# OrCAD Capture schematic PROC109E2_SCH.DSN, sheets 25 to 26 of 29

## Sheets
25 25. SOC_ANALOG_POWER_DECAPs: size C; title: SoC Analog POWER & DECAPs
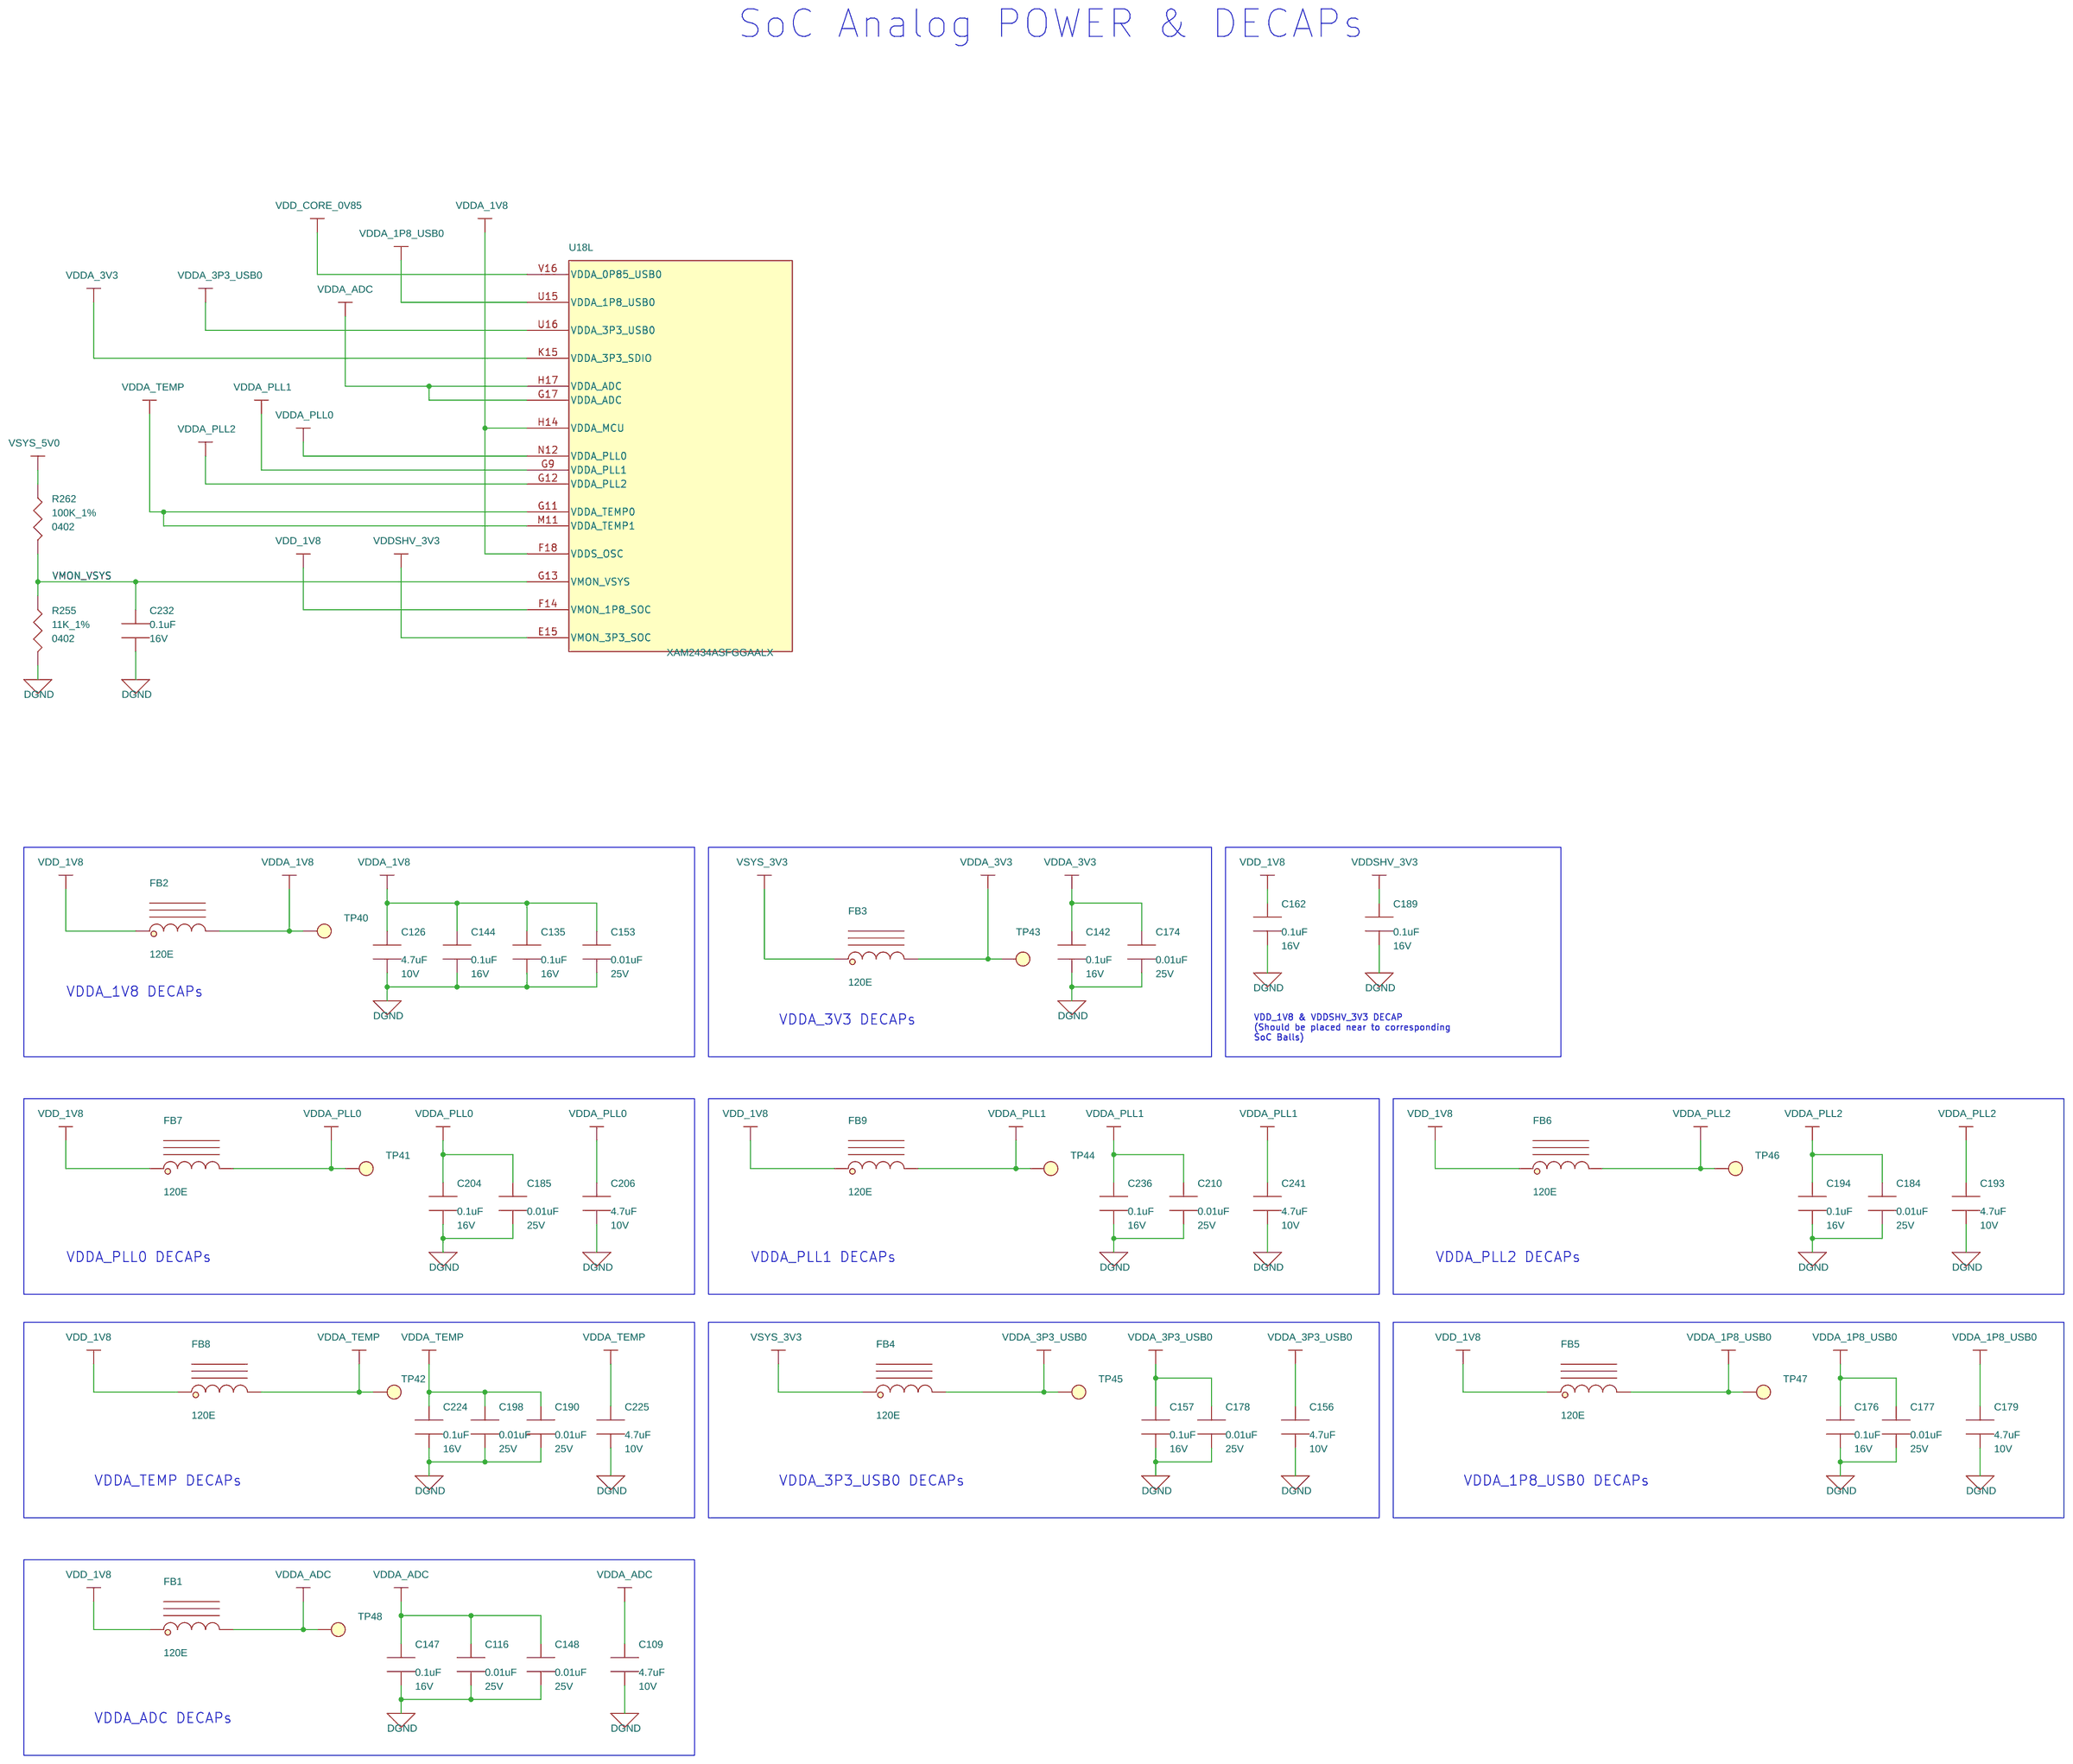
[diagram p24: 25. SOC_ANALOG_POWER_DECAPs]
26 26. BOARD_POWER_IN_TYPE_C: size C; title: BOARD POWER INPUT & USB2.0
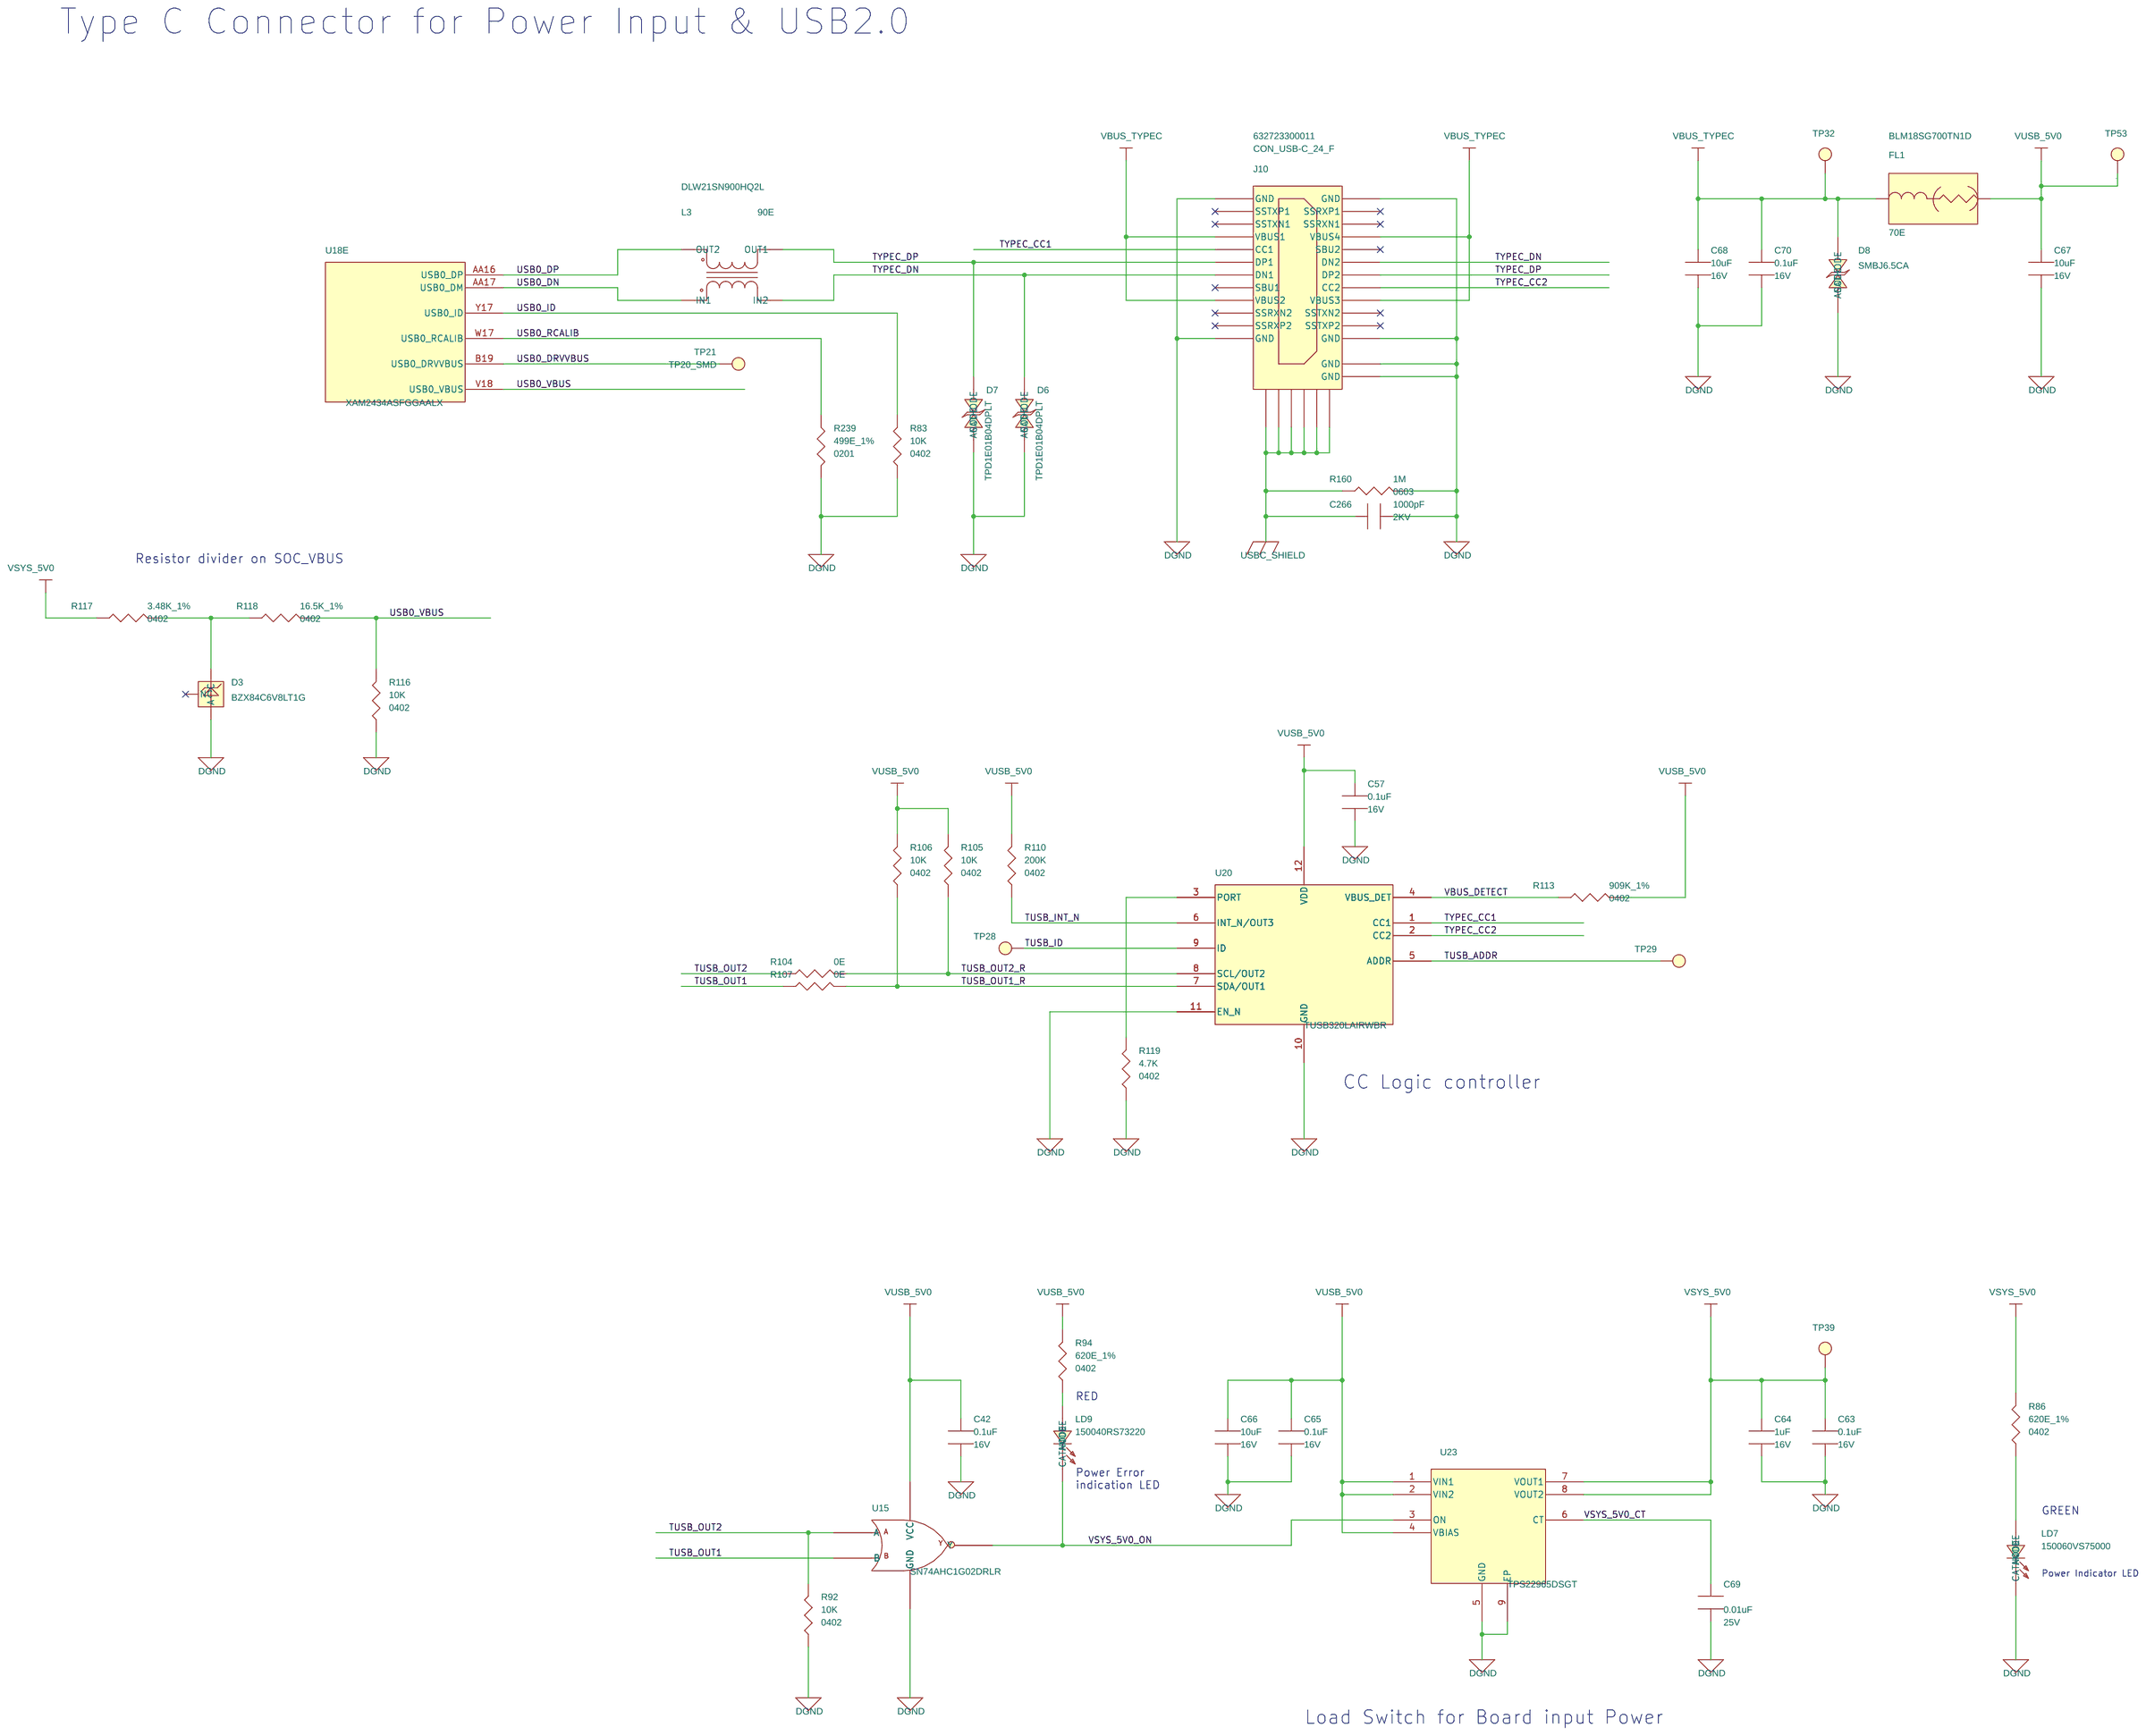
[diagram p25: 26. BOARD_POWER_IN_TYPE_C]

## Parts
sheet 15. SOC_QSPI_BOARD_ID_EEPROM
U18  XAM2434ASFGGAALX  [BGA293_19-68_440X440_1]  (sections A,B,C,D,E,F,G,H,I,J,K,L,M)
sheet 25. SOC_ANALOG_POWER_DECAPs
C109  4.7uF  [CAP0402_0-75]
C116  0.01uF  [CAP0201_0-5]
C126  4.7uF  [CAP0402_0-75]
C135  0.1uF  [CAP0201_0-5]
C142  0.1uF  [CAP0201_0-5]
C144  0.1uF  [CAP0201_0-5]
C147  0.1uF  [CAP0201_0-5]
C148  0.01uF  [CAP0201_0-5]
C153  0.01uF  [CAP0201_0-5]
C156  4.7uF  [CAP0402_0-75]
C157  0.1uF  [CAP0201_0-5]
C162  0.1uF  [CAP0201_0-5]
C174  0.01uF  [CAP0201_0-5]
C176  0.1uF  [CAP0201_0-5]
C177  0.01uF  [CAP0201_0-5]
C178  0.01uF  [CAP0201_0-5]
C179  4.7uF  [CAP0402_0-75]
C184  0.01uF  [CAP0201_0-5]
C185  0.01uF  [CAP0201_0-5]
C189  0.1uF  [CAP0201_0-5]
C190  0.01uF  [CAP0201_0-5]
C193  4.7uF  [CAP0402_0-75]
C194  0.1uF  [CAP0201_0-5]
C198  0.01uF  [CAP0201_0-5]
C204  0.1uF  [CAP0201_0-5]
C206  4.7uF  [CAP0402_0-75]
C210  0.01uF  [CAP0201_0-5]
C224  0.1uF  [CAP0201_0-5]
C225  4.7uF  [CAP0402_0-75]
C232  0.1uF  [CAP0201_0-5]
C236  0.1uF  [CAP0201_0-5]
C241  4.7uF  [CAP0402_0-75]
FB1  120E  [IND0603_1]
FB2  120E  [IND0603_1]
FB3  120E  [IND0603_1]
FB4  120E  [IND0603_1]
FB5  120E  [IND0603_1]
FB6  120E  [IND0603_1]
FB7  120E  [IND0603_1]
FB8  120E  [IND0603_1]
FB9  120E  [IND0603_1]
R255  11K_1%  [RES0402_0-5]
R262  100K_1%  [RES0402_0-5]
TP40  TP20_SMD  [TP20_SMD]
TP41  TP20_SMD  [TP20_SMD]
TP42  TP20_SMD  [TP20_SMD]
TP43  TP20_SMD  [TP20_SMD]
TP44  TP20_SMD  [TP20_SMD]
TP45  TP20_SMD  [TP20_SMD]
TP46  TP20_SMD  [TP20_SMD]
TP47  TP20_SMD  [TP20_SMD]
TP48  TP20_SMD  [TP20_SMD]
sheet 26. BOARD_POWER_IN_TYPE_C
C42  0.1uF  [CAP0201_0-5]
C57  0.1uF  [CAP0201_0-5]
C63  0.1uF  [CAP0201_0-5]
C64  1uF  [CAP0201_0-5]
C65  0.1uF  [CAP0201_0-5]
C66  10uF  [CAP0603_1]
C67  10uF  [CAP0603_1]
C68  10uF  [CAP0603_1]
C69  0.01uF  [CAP0201_0-5]
C70  0.1uF  [CAP0201_0-5]
C266  1000pF  [CAP1210_1-5]
D3  BZX84C6V8LT1G  [SOT23-123_1-2]
D6  TPD1E01B04DPLT  [DIO_DFN0201_0-4]
D7  TPD1E01B04DPLT  [DIO_DFN0201_0-4]
D8  SMBJ6.5CA  [DIO_SMB_2-7]
FL1  70E  [EMIFIL_BLM18B_0603_0-7]
J10  CON_USB-C_24_F  [CON_USBC24_6327233_S_R_S_3-1]
L3  90E  [IND4_DLW21H_90X60_SMD_1-4]
LD7  150060VS75000  [LED_150060SS75000_70X40_SMD_0-8]
LD9  150040RS73220  [LED_150040GS73220_40X20_SMD_0-4]
R83  10K  [RES0402_0-5]
R86  620E_1%  [RES0402_0-5]
R92  10K  [RES0402_0-5]
R94  620E_1%  [RES0402_0-5]
R104  0E  [RES0402_0-5]
R105  10K  [RES0402_0-5]
R106  10K  [RES0402_0-5]
R107  0E  [RES0402_0-5]
R110  200K  [RES0402_0-5]
R113  909K_1%  [RES0402_0-5]
R116  10K  [RES0402_0-5]
R117  3.48K_1%  [RES0402_0-5]
R118  16.5K_1%  [RES0402_0-5]
R119  4.7K  [RES0402_0-5]
R160  1M  [RES0603_0-75]
R239  499E_1%  [RES0201_0-5]
TP21  TP20_SMD  [TP20_SMD]
TP28  TP20_SMD  [TP20_SMD]
TP29  TP20_SMD  [TP20_SMD]
TP32  TP40_SMD  [TP40_SMD]
TP39  TP40_SMD  [TP40_SMD]
TP53  TP40_SMD  [TP40_SMD]
U15  SN74AHC1G02DRLR  [SOT553-5_0-6]
U20  TUSB320LAIRWBR  [X2QFN12_TUSB322I_60X60_0-4]
U23  TPS22965DSGT  [WSON8_19-68_80X80_0-8]

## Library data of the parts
U18 = AM243X_SOC_LP_EVM_BGA293: IC AM243x SoC_LP_EVM MICROPROCESSOR BGA293; Chkd/date: MANIRAJA/131120; Crtd /date: ALVY/121120; Custom_Duty: 15%; Customs_HS_Code: 85423100; Distributor_name: NA; Distributor_part_number: NA; Footprint Path: Y:\MIS_DATABASE\Library\ALTIUM_TOOL\PCB_FOOTPRINTS\Altium_Footprint_Lib.PcbLib; Height: 1.00MM; Library Path: Y:\MIS_DATABASE\Library\ALTIUM_TOOL\SCHEMATICS_PARTS\MS_MICROPROCESSOR_Library.schlib; Library Ref: AM243x SoC_LP_EVM_BGA293; Mfr_name: TEXAS INSTRUMENTS; Mistral Part No: 141220110003; Package: BGA293; Part_type: ICS\DIGITAL\MICROPROCESSOR; Project: TI_AM243x LP EVM; RoHS: NA; Temperature: NA; Tolerance: NA; Voltage: NA; Wattage: NA; Weight: NA; Datasheet: Y:\MIS_DATABASE\DATASHEETS\ICS\DIGITAL\MICROCONTROLLER\AM243x SoC-FP.PDF
C109 C126 C156 C179 C193 C206 C225 C241 = CAP: CAP CERAMIC 4.7uF 10V 20% X5R 0402; Chkd/date: MANIRAJA/110718; Crtd /date: ALVY/110718; Custom_Duty: 15%; Customs_HS_Code: 85322990; Distributor_name: DIGIKEY; Distributor_part_number: 490-14306-1-ND; Footprint Path: Y:\MIS_DATABASE\Library\ALTIUM_TOOL\PCB_FOOTPRINTS\Altium_Footprint_Lib.PcbLib; Height: 0.65MM; Library Path: Y:\MIS_DATABASE\Library\ALTIUM_TOOL\SCHEMATICS_PARTS\MS_DISCRETE_Library.schlib; Mfr_name: MURATA; Mfr_part_number: GRM155R61A475MEAAD; Mistral Part No: 120012060002-R; Package: 0402; Part_type: CAPACITORS\CERAMIC; Project: TI_J7SVB_PCIE_ADD-ON-CARD; RoHS: RoHS; Temperature: -55°C+85°C; Tolerance: 20%; Voltage: 10V; Wattage: NA; Weight: 14mg; Datasheet: Y:\MIS_DATABASE\DATASHEETS\CAPACITORS\GRM155R61A475MEAAD.PDF
C69 C116 C148 C153 C174 C177 C178 C184 C185 C190 C198 C210 = CAP: CAP CERAMIC 0.01uF 25V 10% X7R 0201; Chkd/date: MANIRAJA/080519; Crtd /date: ALVY/080519; Custom_Duty: 15%; Customs_HS_Code: 85322990; Distributor_name: DIGIKEY; Distributor_part_number: 490-14454-1-ND; Footprint Path: Y:\MIS_DATABASE\Library\ALTIUM_TOOL\PCB_FOOTPRINTS\Altium_Footprint_Lib.PcbLib; Height: 0.33MM; Library Path: Y:\MIS_DATABASE\Library\ALTIUM_TOOL\SCHEMATICS_PARTS\MS_DISCRETE_Library.schlib; Mfr_name: MURATA; Mfr_part_number: GRM033R71E103KE14D; Mistral Part No: 120019050002-R; Package: 0201; Part_type: CAPACITORS\CERAMIC; Project: BRUKER_SD820_COMMONDO; RoHS: RoHS; Temperature: -55°C+125°C; Tolerance: 10%; Voltage: 25V; Wattage: NA; Weight: 0.33mg; Datasheet: Y:\MIS_DATABASE\DATASHEETS\CAPACITORS\GRM033R71E103KE14.PDF
C42 C57 C63 C65 C70 C135 C142 C144 C147 C157 C162 C176 C189 C194 C204 C224 C232 C236 = CAP: CAP CERAMIC 0.1uF 16V 10% X5R 0201; Chkd/date: MANIRAJA/230118; Crtd /date: MANIRAJA/230118; Custom_Duty: 15%; Customs_HS_Code: 85322990; Distributor_name: DIGIKEY; Distributor_part_number: 490-14305-1-ND; Footprint Path: Y:\MIS_DATABASE\Library\ALTIUM_TOOL\PCB_FOOTPRINTS\Altium_Footprint_Lib.PcbLib; Height: 0.33MM; Library Path: Y:\MIS_DATABASE\Library\ALTIUM_TOOL\SCHEMATICS_PARTS\MS_DISCRETE_Library.schlib; Mfr_name: MURATA; Mfr_part_number: GRM033R61C104KE14D; Mistral Part No: 120009030072-R; Package: 0201; Part_type: CAPACITORS\CERAMIC; Project: TI_MAXIE_CPB; RoHS: RoHS; Temperature: -55°C+85°C; Tolerance: 10%; Voltage: 16V; Wattage: NA; Weight: 0.33mg; Datasheet: Y:\MIS_DATABASE\DATASHEETS\CAPACITORS\GRM033R61C104KE14.PDF
FB1-FB9 = INDUCTOR_FERRITE: IND FERRITE BEAD CHIP 120E 2A 0603; Chkd/date: MANIRAJA/180820; Crtd /date: ALVY/180820; Custom_Duty: 24%; Customs_HS_Code: 85437099; Distributor_name: DIGIKEY; Distributor_part_number: 732-782631141CT-ND; Footprint Path: Y:\MIS_DATABASE\Library\ALTIUM_TOOL\PCB_FOOTPRINTS\Altium_Footprint_Lib.PcbLib; Height: 1.00MM; Library Path: Y:\MIS_DATABASE\Library\ALTIUM_TOOL\SCHEMATICS_PARTS\MS_FILTER_Library.schlib; Mfr_name: WURTH ELECTRONICS; Mfr_part_number: 782631141; Mistral Part No: 130020080015-R; Package: 0603; Part_type: INDUCTOR; Project: AM64x_EVM_BRD; RoHS: RoHS; Temperature: -55°C+125°C; Tolerance: 25%; Voltage: NA; Wattage: NA; Weight: NA; Datasheet: Y:\MIS_DATABASE\DATASHEETS\DISCRETES\INDUCTORS\782631141.PDF
R255 = RESISTOR: RES 11K 1/16W 1% 0402; Chkd/date: VASANTHA/251115; Crtd /date: VASANTHA/251115; Custom_Duty: 15%; Customs_HS_Code: 85332119; Distributor_name: DIGIKEY; Distributor_part_number: 311-11.0KLRCT-ND; Footprint Path: Y:\MIS_DATABASE\Library\ALTIUM_TOOL\PCB_FOOTPRINTS\Altium_Footprint_Lib.PcbLib; Height: 0.40MM; Library Path: Y:\MIS_DATABASE\Library\ALTIUM_TOOL\SCHEMATICS_PARTS\MS_DISCRETE_Library.schlib; Mfr_name: YAGEO AMERICA; Mfr_part_number: RC0402FR-0711KL; Mistral Part No: 110015110012-R; Package: 0402; Part_type: RESISTORS\FIXED; Project: TI_VLAN_SWITCH; RoHS: RoHS; Temperature: -55°C+155°C; Tolerance: 1%; Voltage: NA; Wattage: 1/16W; Weight: 0.65mg; Datasheet: Y:\MIS_DATABASE\DATASHEETS\RESISTORS\RCXXXXL-SER_MAR18.PDF
R262 = RESISTOR: RES 100K 1/16W 1% 0402; Chkd/date: MANIRAJA/110917; Crtd /date: MANIRAJA/110917; Custom_Duty: 15%; Customs_HS_Code: 85332119; Distributor_name: DIGIKEY; Distributor_part_number: 311-100KLRCT-ND; Footprint Path: Y:\MIS_DATABASE\Library\ALTIUM_TOOL\PCB_FOOTPRINTS\Altium_Footprint_Lib.PcbLib; Height: 0.40MM; Library Path: Y:\MIS_DATABASE\Library\ALTIUM_TOOL\SCHEMATICS_PARTS\MS_DISCRETE_Library.schlib; Mfr_name: YAGEO AMERICA; Mfr_part_number: RC0402FR-07100KL; Mistral Part No: 110014060043-R; Package: 0402; Part_type: RESISTORS\FIXED; Project: CRADE RF CARD; RoHS: RoHS; Temperature: -55°C+155°C; Tolerance: 1%; Voltage: NA; Wattage: 1/16W; Weight: 0.65mg; Datasheet: Y:\MIS_DATABASE\DATASHEETS\RESISTORS\RCXXXXL-SER_MAR18.PDF
TP21 TP28 TP29 TP40-TP48 = TESTPOINT: TESTPOINT CIR 20 SMD; Chkd/date: SHREESHAIL/171006; Crtd /date: MAZHAR/171006; Custom_Duty: NA; Customs_HS_Code: NA; Distributor_name: NA; Distributor_part_number: NA; Footprint Path: Y:\MIS_DATABASE\Library\ALTIUM_TOOL\PCB_FOOTPRINTS\Altium_Footprint_Lib.PcbLib; Height: NA; Library Path: Y:\MIS_DATABASE\Library\ALTIUM_TOOL\SCHEMATICS_PARTS\MS_DISCRETE_Library.schlib; MECHANICAL 3D STEP FILE: NA; Mfr_name: LOCAL; Mistral Part No: NA; Package: SMD; Project: BT MODULE_CSRBC04; RoHS: NA; Temperature: NA; Tolerance: NA; Voltage: NA; Wattage: NA; Weight: NA; Datasheet: NA
C64 = CAP: CAP CERAMIC 1uF 16V 20% X5R 0201; Chkd/date: MANIRAJA/300520; Crtd /date: ALVY/260520; Custom_Duty: 15%; Customs_HS_Code: 85322990; Distributor_name: DIGIKEY; Distributor_part_number: 490-18654-1-ND; Footprint Path: Y:\MIS_DATABASE\Library\ALTIUM_TOOL\PCB_FOOTPRINTS\Altium_Footprint_Lib.PcbLib; Height: 0.39MM; Library Path: Y:\MIS_DATABASE\Library\ALTIUM_TOOL\SCHEMATICS_PARTS\MS_DISCRETE_Library.schlib; Mfr_name: MURATA; Mfr_part_number: GRM033R61C105ME15D; Mistral Part No: 120018090038-R; Package: 0201; Part_type: CAPACITORS\CERAMIC; Project: QCS610_NANOSOM; RoHS: RoHS; Temperature: -55°C+85°C; Tolerance: 20%; Voltage: 16V; Wattage: NA; Weight: 0.33mg; Datasheet: Y:\MIS_DATABASE\DATASHEETS\CAPACITORS\GRM033R61C105ME15.PDF
C66-C68 = CAP: CAP CERAMIC 10uF 16V 20% X5R 0603; Chkd/date: MANIRAJA/130617; Crtd /date: USMAN/151013; Custom_Duty: 15%; Customs_HS_Code: 85322990; Distributor_name: DIGIKEY; Distributor_part_number: 490-7201-1-ND; Footprint Path: Y:\MIS_DATABASE\Library\ALTIUM_TOOL\PCB_FOOTPRINTS\Altium_Footprint_Lib.PcbLib; Height: 0.90MM; Library Path: Y:\MIS_DATABASE\Library\ALTIUM_TOOL\SCHEMATICS_PARTS\MS_DISCRETE_Library.schlib; Mfr_name: MURATA; Mfr_part_number: GRM188R61C106MA73D; Mistral Part No: 120013100015-R; Package: 0603; Part_type: CAPACITORS\CERAMIC; Project: C-BAND_SYNTH; RoHS: RoHS; Temperature: -55°C+85°C; Tolerance: 20%; Voltage: 16V; Wattage: NA; Weight: 6.3mg; Datasheet: Y:\MIS_DATABASE\DATASHEETS\CAPACITORS\MURATA-GXX-SER_NOV17.PDF
C266 = CAP: CAP CERAMIC 1000pF 2KV 10% X7R 1210; Chkd/date: ALVY/071220; Crtd /date: MANIRAJA/071220; Custom_Duty: 15%; Customs_HS_Code: 85322990; Distributor_name: DIGIKEY; Distributor_part_number: 732-12130-1-ND; Footprint Path: Y:\MIS_DATABASE\Library\ALTIUM_TOOL\PCB_FOOTPRINTS\Altium_Footprint_Lib.PcbLib; Height: 1.35MM; Library Path: Y:\MIS_DATABASE\Library\ALTIUM_TOOL\SCHEMATICS_PARTS\MS_DISCRETE_Library.schlib; Mfr_name: WURTH ELEKTRONIK; Mfr_part_number: 885342209009; Mistral Part No: 120020120008-R; Package: 1210; Part_type: CAPACITORS\CERAMIC; Project: TI_AM243x LP EVM; RoHS: RoHS; Temperature: -55°C+125°C; Tolerance: 10%; Voltage: 2KV; Wattage: NA; Weight: 19.234mg; Datasheet: Y:\MIS_DATABASE\DATASHEETS\CAPACITORS\885342209009.PDF
D3 = DIODE_ZENER_SOT23_13: DIODE ZENER 250mW 6.8V SOT23-123; Chkd/date: MANIRAJA/031017; Crtd /date: MANIRAJA/031017; Custom_Duty: 15%; Customs_HS_Code: 85412900; Distributor_name: DIGIKEY; Distributor_part_number: BZX84C6V8LT1GOSCT-ND; Height: 1.11MM; Mfr_name: ON SEMICONDUCTOR; Mistral Part No: 130017100002-R; Package: SOT23-123; Part_type: DIODE\ZENER; Project: TI_MAXIE_CPB; RoHS: RoHS; Temperature: -65°C+150°C; Tolerance: NA; Voltage: 6.8V; Wattage: NA; Weight: 8mg; Datasheet: Y:\MIS_DATABASE\DATASHEETS\DISCRETES\DIODES\BZX84XX.PDF
D6 D7 = DIODE_TVS_DUAL: DIODE 1CH ESD PROTECTION FOR USB TYPE-C AND THUNDERBOLT3 X2SON2; Chkd/date: MANIRAJA/230920; Crtd /date: ALVY/230920; Custom_Duty: 15%; Customs_HS_Code: 85412900; Distributor_name: DIGIKEY; Distributor_part_number: 296-44484-1-ND; Footprint Path: Y:\MIS_DATABASE\Library\ALTIUM_TOOL\PCB_FOOTPRINTS\Altium_Footprint_Lib.PcbLib; Height: 0.32MM; Library Path: Y:\MIS_DATABASE\Library\ALTIUM_TOOL\SCHEMATICS_PARTS\MS_DISCRETE_Library.schlib; Mfr_name: TEXAS INSTRUMENTS; Mistral Part No: 130020090037-R; Package: X2SON2; Part_type: DIODE\TVS; Project: AM64X_SKEVM; RoHS: RoHS; Temperature: -40°C+125°C; Tolerance: NA; Voltage: NA; Wattage: NA; Weight: 0.2mg; Datasheet: Y:\MIS_DATABASE\DATASHEETS\DISCRETES\DIODES\TPD1E01B04.PDF
D8 = DIODE_TVS_DUAL: DIODE TVS BI-DIR 6.5V 600W SMB; Chkd/date: MANIRAJA/240521; Crtd /date: ALVY/210521; Custom_Duty: 15%; Customs_HS_Code: 85412900; Distributor_name: DIGIKEY; Distributor_part_number: SMBJ6.5CA-TPMSCT-ND; Footprint Path: Y:\MIS_DATABASE\Library\ALTIUM_TOOL\PCB_FOOTPRINTS\Altium_Footprint_Lib.PcbLib; Height: 2.62MM; Library Path: Y:\MIS_DATABASE\Library\ALTIUM_TOOL\SCHEMATICS_PARTS\MS_DISCRETE_Library.schlib; Mfr_name: MCC; Mfr_part_number: SMBJ6.5CA-TP; Mistral Part No: 130021050009-R; Package: SMB; Part_type: DIODE\TVS; Project: AM243x_LP_BRD; RoHS: RoHS; Temperature: -55°C+175°C; Tolerance: NA; Voltage: 6.5V; Wattage: 600W; Weight: 93mg; Datasheet: Y:\MIS_DATABASE\DATASHEETS\DISCRETES\DIODES\MCC-SMBJ5-440.PDF
FL1 = EMIFILTER_IND: IND FERRITE BEAD CHIP 70E 4A 0603; Chkd/date: MANIRAJA/151020; Crtd /date: ALVY/141020; Custom_Duty: 24%; Customs_HS_Code: 85437099; Distributor_name: DIGIKEY; Distributor_part_number: 490-5224-1-ND; Footprint Path: Y:\MIS_DATABASE\Library\ALTIUM_TOOL\PCB_FOOTPRINTS\Altium_Footprint_Lib.PcbLib; Height: 0.65MM; Library Path: Y:\MIS_DATABASE\Library\ALTIUM_TOOL\SCHEMATICS_PARTS\MS_DISCRETE_Library.schlib; Mfr_name: MURATA; Mfr_part_number: BLM18SG700TN1D; Mistral Part No: 130020100039-R; Package: 0603; Part_type: INDUCTOR; Project: AM64X_SKEVM; RoHS: RoHS; Temperature: -55°C+125°C; Tolerance: 25%; Voltage: NA; Wattage: NA; Weight: 5mg; Datasheet: Y:\MIS_DATABASE\DATASHEETS\DISCRETES\INDUCTORS\BLM18XX-N1X.PDF
J10 = CON_USB-C_24_6327233: CON USB-C TYPE 24POS FEMALE RT SMD; Chkd/date: MANIRAJA/020817; Crtd /date: MANIRAJA/020817; Custom_Duty: 24%; Customs_HS_Code: 85369090; Distributor_name: DIGIKEY; Distributor_part_number: 732-9618-1-ND; Height: 3.06MM; Mfr_name: WURTH ELECTRONICS; Mfr_part_number: 632723300011; Mistral Part No: 150017080002-R; Package: SMD; Part_type: CONNECTOR\USB; Project: SD820_NANO_SOM; RoHS: RoHS; Temperature: -25°C+105°C; Tolerance: NA; Voltage: NA; Wattage: NA; Weight: NA; Datasheet: Y:\MIS_DATABASE\DATASHEETS\CONNECTORS\632723300011.PDF
L3 = INDUCTOR_DLW31S: IND COMMON MODE CHOKE 90E 280mA SMD; Chkd/date: MANIRAJA/280121; Crtd /date: ALVY/280121; Custom_Duty: 24%; Customs_HS_Code: 85437099; Distributor_name: DIGIKEY; Distributor_part_number: 490-5134-1-ND; Footprint Path: Y:\MIS_DATABASE\Library\ALTIUM_TOOL\PCB_FOOTPRINTS\Altium_Footprint_Lib.PcbLib; Height: 1.40MM; Library Path: Y:\MIS_DATABASE\Library\ALTIUM_TOOL\SCHEMATICS_PARTS\MS_DISCRETE_Library.schlib; Mfr_name: MURATA; Mfr_part_number: DLW21SN900HQ2L; Mistral Part No: 130021010048-R; Package: SMD; Part_type: INDUCTOR; Project: TI_AM243x LP EVM; RoHS: RoHS; Temperature: -40°C+85°C; Tolerance: 25%; Voltage: NA; Wattage: NA; Weight: 11mg; Datasheet: Y:\MIS_DATABASE\DATASHEETS\DISCRETES\INDUCTORS\DLW21SN-HQ2.PDF
LD7 = DIODE_LED: DIODE LED BRIGHT GREEN SMD; Chkd/date: MANIRAJA/220720; Crtd /date: ALVY/210720; Custom_Duty: 24%; Customs_HS_Code: 85439000; Distributor_name: DIGIKEY; Distributor_part_number: 732-4980-1-ND; Footprint Path: Y:\MIS_DATABASE\Library\ALTIUM_TOOL\PCB_FOOTPRINTS\Altium_Footprint_Lib.PcbLib; Height: 0.80MM; Library Path: Y:\MIS_DATABASE\Library\ALTIUM_TOOL\SCHEMATICS_PARTS\MS_OPTO_Library.schlib; Mfr_name: WURTH ELECTRONICS; Mistral Part No: 130020070019-R; Package: SMD; Part_type: OPTO\LED; Project: AM64x-IO LINK BRD; RoHS: RoHS; Temperature: -40°C+85°C; Tolerance: NA; Voltage: NA; Wattage: NA; Weight: 25mg; Datasheet: Y:\MIS_DATABASE\DATASHEETS\DISCRETES\LEDS\150060VS75000.PDF
LD9 = DIODE_LED: DIODE LED RED SMD; Chkd/date: MANIRAJA/100920; Crtd /date: ALVY/100920; Custom_Duty: 24%; Customs_HS_Code: 85439000; Distributor_name: DIGIKEY; Distributor_part_number: 732-13422-1-ND; Footprint Path: Y:\MIS_DATABASE\Library\ALTIUM_TOOL\PCB_FOOTPRINTS\Altium_Footprint_Lib.PcbLib; Height: 0.35MM; Library Path: Y:\MIS_DATABASE\Library\ALTIUM_TOOL\SCHEMATICS_PARTS\MS_OPTO_Library.schlib; Mfr_name: WURTH ELECTRONICS; Mistral Part No: 130020090020-R; Package: SMD; Part_type: OPTO\LED; Project: AM64X_SKEVM; RoHS: RoHS; Temperature: -40°C+85°C; Tolerance: NA; Voltage: NA; Wattage: NA; Weight: 29.3mg; Datasheet: Y:\MIS_DATABASE\DATASHEETS\DISCRETES\LEDS\150040RS73220.PDF
R83 R92 R105 R106 R116 = RESISTOR: RES 10K 1/16W 5% 0402; Chkd/date: VASANTHA/061216; Crtd /date: MAZHAR/230805; Custom_Duty: 15%; Customs_HS_Code: 85332119; Distributor_name: DIGIKEY; Distributor_part_number: 311-10KJRCT-ND; Footprint Path: Y:\MIS_DATABASE\Library\ALTIUM_TOOL\PCB_FOOTPRINTS\Altium_Footprint_Lib.PcbLib; Height: 0.40MM; Library Path: Y:\MIS_DATABASE\Library\ALTIUM_TOOL\SCHEMATICS_PARTS\MS_DISCRETE_Library.schlib; Mfr_name: YAGEO AMERICA; Mfr_part_number: RC0402JR-0710KL; Mistral Part No: 110011060021-R; Package: 0402; Part_type: RESISTORS\FIXED; Project: HSE; RoHS: RoHS; Temperature: -55°C+155°C; Tolerance: 5%; Voltage: NA; Wattage: 1/16W; Weight: 0.65mg; Datasheet: Y:\MIS_DATABASE\DATASHEETS\RESISTORS\RCXXXXL-SER_MAR18.PDF
R86 R94 = RESISTOR: RES 620E 1/16W 1% 0402; Chkd/date: ALVY/091220; Crtd /date: MANIRAJA/091220; Custom_Duty: 15%; Customs_HS_Code: 85332119; Distributor_name: DIGIKEY; Distributor_part_number: 311-620LRCT-ND; Footprint Path: Y:\MIS_DATABASE\Library\ALTIUM_TOOL\PCB_FOOTPRINTS\Altium_Footprint_Lib.PcbLib; Height: 0.40MM; Library Path: Y:\MIS_DATABASE\Library\ALTIUM_TOOL\SCHEMATICS_PARTS\MS_DISCRETE_Library.schlib; Mfr_name: YAGEO AMERICA; Mfr_part_number: RC0402FR-07620RL; Mistral Part No: 110020120009-R; Package: 0402; Part_type: RESISTORS\FIXED; Project: TI_AM243x LP EVM; RoHS: RoHS; Temperature: -55°C+155°C; Tolerance: 1%; Voltage: NA; Wattage: 1/16W; Weight: 0.65mg; Datasheet: Y:\MIS_DATABASE\DATASHEETS\RESISTORS\RCXXXXL-SER_MAR18.PDF
R104 R107 = RESISTOR: RES 0E 1/16W 5% 0402; Chkd/date: VASANTHA/291216; Crtd /date: CHAITHANYA/300911; Custom_Duty: 15%; Customs_HS_Code: 85332119; Distributor_name: DIGIKEY; Distributor_part_number: 311-0.0JRCT-ND; Footprint Path: Y:\MIS_DATABASE\Library\ALTIUM_TOOL\PCB_FOOTPRINTS\Altium_Footprint_Lib.PcbLib; Height: 0.40MM; Library Path: Y:\MIS_DATABASE\Library\ALTIUM_TOOL\SCHEMATICS_PARTS\MS_DISCRETE_Library.schlib; Mfr_name: YAGEO AMERICA; Mfr_part_number: RC0402JR-070RL; Mistral Part No: 110011090036-R; Package: 0402; Part_type: RESISTORS\FIXED; Project: VP-4000-PROCESSOR; RoHS: RoHS; Temperature: -55°C+155°C; Tolerance: 5%; Voltage: NA; Wattage: 1/16W; Weight: 0.65mg; Datasheet: Y:\MIS_DATABASE\DATASHEETS\RESISTORS\RCXXXXL-SER_MAR18.PDF
R110 = RESISTOR: RES 200K 1/10W 5% 0402; Chkd/date: MANOJ/230414; Crtd /date: USMAN/151013; Custom_Duty: 15%; Customs_HS_Code: 85332119; Distributor_name: DIGIKEY; Distributor_part_number: P200KJCT-ND; Footprint Path: Y:\MIS_DATABASE\Library\ALTIUM_TOOL\PCB_FOOTPRINTS\Altium_Footprint_Lib.PcbLib; Height: 0.40MM; Library Path: Y:\MIS_DATABASE\Library\ALTIUM_TOOL\SCHEMATICS_PARTS\MS_DISCRETE_Library.schlib; Mfr_name: PANASONIC-ECG; Mfr_part_number: ERJ-2GEJ204X; Mistral Part No: 110013100006-R; Package: 0402; Part_type: RESISTORS\FIXED; Project: C-BAND_SYNTH; RoHS: RoHS; Temperature: -55°C+155°C; Tolerance: 5%; Voltage: NA; Wattage: 1/10W; Weight: 0.8mg; Datasheet: Y:\MIS_DATABASE\DATASHEETS\RESISTORS\PAN-ERJSER_NOV17.PDF
R113 = RESISTOR: RES 909K 1/16W 1% 0402; Chkd/date: RAGESH/110511; Crtd /date: BAVISH/100511; Cust_part_number: 4700-80053E; Custom_Duty: 15%; Customs_HS_Code: 85332119; Distributor_name: DIGIKEY; Distributor_part_number: 541-909KLCT-ND; Footprint Path: Y:\MIS_DATABASE\Library\ALTIUM_TOOL\PCB_FOOTPRINTS\Altium_Footprint_Lib.PcbLib; Height: 0.40MM; Library Path: Y:\MIS_DATABASE\Library\ALTIUM_TOOL\SCHEMATICS_PARTS\MS_DISCRETE_Library.schlib; Mfr_name: VISHAY; Mfr_part_number: CRCW0402909KFKED; Mistral Part No: 110011050007-R; Package: 0402; Part_type: RESISTORS\FIXED; Project: ITS-SINGAL_COND_CARD; RoHS: RoHS; Temperature: -55°C+155°C; Tolerance: 1%; Voltage: NA; Wattage: 1/16W; Weight: 0.65mg; Datasheet: Y:\MIS_DATABASE\DATASHEETS\RESISTORS\CRCW0603.PDF
R117 = RESISTOR: RES 3.48K 1/16W 1% 0402; Chkd/date: ALVY/091220; Crtd /date: MANIRAJA/091220; Custom_Duty: 15%; Customs_HS_Code: 85332119; Distributor_name: DIGIKEY; Distributor_part_number: YAG3148CT-ND; Footprint Path: Y:\MIS_DATABASE\Library\ALTIUM_TOOL\PCB_FOOTPRINTS\Altium_Footprint_Lib.PcbLib; Height: 0.40MM; Library Path: Y:\MIS_DATABASE\Library\ALTIUM_TOOL\SCHEMATICS_PARTS\MS_DISCRETE_Library.schlib; Mfr_name: YAGEO AMERICA; Mfr_part_number: RC0402FR-073K48L; Mistral Part No: 110019120035-R; Package: 0402; Part_type: RESISTORS\FIXED; Project: TI_AM243x LP EVM; RoHS: RoHS; Temperature: -55°C+155°C; Tolerance: 1%; Voltage: NA; Wattage: 1/16W; Weight: 0.65mg; Datasheet: Y:\MIS_DATABASE\DATASHEETS\RESISTORS\RCXXXXL-SER_MAR18.PDF
R118 = RESISTOR: RES 16.5K 1/16W 1% 0402; Chkd/date: ALVY/091220; Crtd /date: MANIRAJA/091220; Custom_Duty: 15%; Customs_HS_Code: 85332119; Distributor_name: DIGIKEY; Distributor_part_number: YAG3002CT-ND; Footprint Path: Y:\MIS_DATABASE\Library\ALTIUM_TOOL\PCB_FOOTPRINTS\Altium_Footprint_Lib.PcbLib; Height: 0.40MM; Library Path: Y:\MIS_DATABASE\Library\ALTIUM_TOOL\SCHEMATICS_PARTS\MS_DISCRETE_Library.schlib; Mfr_name: YAGEO AMERICA; Mfr_part_number: RC0402FR-0716K5L; Mistral Part No: 110020120011-R; Package: 0402; Part_type: RESISTORS\FIXED; Project: TI_AM243x LP EVM; RoHS: RoHS; Temperature: -55°C+155°C; Tolerance: 1%; Voltage: NA; Wattage: 1/16W; Weight: 0.65mg; Datasheet: Y:\MIS_DATABASE\DATASHEETS\RESISTORS\RCXXXXL-SER_MAR18.PDF
R119 = RESISTOR: RES 4.7K 1/16W 5% 0402; Chkd/date: VASANTHA/130516; Crtd /date: VASANTHA/130516; Custom_Duty: 15%; Customs_HS_Code: 85332119; Distributor_name: DIGIKEY; Distributor_part_number: 311-4.7KJRCT-ND; Footprint Path: Y:\MIS_DATABASE\Library\ALTIUM_TOOL\PCB_FOOTPRINTS\Altium_Footprint_Lib.PcbLib; Height: 0.40MM; Library Path: Y:\MIS_DATABASE\Library\ALTIUM_TOOL\SCHEMATICS_PARTS\MS_DISCRETE_Library.schlib; Mfr_name: YAGEO AMERICA; Mfr_part_number: RC0402JR-074K7L; Mistral Part No: 110011060001-R; Package: 0402; Part_type: RESISTORS\FIXED; Project: TMDXCSK368; RoHS: RoHS; Temperature: -55°C+155°C; Tolerance: 5%; Voltage: NA; Wattage: 1/16W; Weight: 0.65mg; Datasheet: Y:\MIS_DATABASE\DATASHEETS\RESISTORS\RCXXXXL-SER_MAR18.PDF
R160 = RESISTOR: RES 1M 1/10W 5% 0603; Chkd/date: ALVY/091220; Crtd /date: MANIRAJA/091220; Custom_Duty: 15%; Customs_HS_Code: 85332119; Distributor_name: DIGIKEY; Distributor_part_number: 311-1.0MGRCT-ND; Footprint Path: Y:\MIS_DATABASE\Library\ALTIUM_TOOL\PCB_FOOTPRINTS\Altium_Footprint_Lib.PcbLib; Height: 0.55MM; Library Path: Y:\MIS_DATABASE\Library\ALTIUM_TOOL\SCHEMATICS_PARTS\MS_DISCRETE_Library.schlib; Mfr_name: YAGEO AMERICA; Mfr_part_number: RC0603JR-071ML; Mistral Part No: 110009030413-R; Package: 0603; Part_type: RESISTORS\FIXED; Project: TI_AM243x LP EVM; RoHS: RoHS; Temperature: -55°C+155°C; Tolerance: 5%; Voltage: NA; Wattage: 1/10W; Weight: 2mg; Datasheet: Y:\MIS_DATABASE\DATASHEETS\RESISTORS\RCXXXXL-SER_MAR18.PDF
R239 = RESISTOR: RES 499E 1/20W 1% 0201; Chkd/date: ALVY/091220; Crtd /date: MANIRAJA/091220; Custom_Duty: 15%; Customs_HS_Code: 85332119; Distributor_name: DIGIKEY; Distributor_part_number: YAG2700CT-ND; Footprint Path: Y:\MIS_DATABASE\Library\ALTIUM_TOOL\PCB_FOOTPRINTS\Altium_Footprint_Lib.PcbLib; Height: 0.26MM; Library Path: Y:\MIS_DATABASE\Library\ALTIUM_TOOL\SCHEMATICS_PARTS\MS_DISCRETE_Library.schlib; Mfr_name: YAGEO AMERICA; Mfr_part_number: RC0201FR-07499RL; Mistral Part No: 110009030907-R; Package: 0201; Part_type: RESISTORS\FIXED; Project: TI_AM243x LP EVM; RoHS: RoHS; Temperature: -55°C+125°C; Tolerance: 1%; Voltage: NA; Wattage: 1/20W; Weight: 0.17mg; Datasheet: Y:\MIS_DATABASE\DATASHEETS\RESISTORS\RCXXXXL-SER_MAR18.PDF
TP32 TP39 TP53 = TESTPOINT: TESTPOINT CIR 40 SMD; Chkd/date: MAZHAR/190505; Crtd /date: MAZHAR/190505; Distributor_name: NA; Distributor_part_number: NA; Footprint Path: Y:\MIS_DATABASE\Library\ALTIUM_TOOL\PCB_FOOTPRINTS\Altium_Footprint_Lib.PcbLib; Height: NA; Library Path: Y:\MIS_DATABASE\Library\ALTIUM_TOOL\SCHEMATICS_PARTS\MS_DISCRETE_Library.schlib; MECHANICAL 3D STEP FILE: NA; Mfr_name: LOCAL; Mistral Part No: 130009030933; Package: SMD; Project: RAINIER-3; RoHS: NA; Temperature: NA; Tolerance: NA; Voltage: NA; Wattage: NA; Weight: NA; Datasheet: NA
U15 = SN74AHC1G02DBV_SOT23-5: IC SINGLE 2-INPUT POSITIVE-NOR GATE SOT553-5; Chkd/date: MANIRAJA/141020; Crtd /date: ALVY/131020; Custom_Duty: 15%; Customs_HS_Code: 85423100; Distributor_name: DIGIKEY; Distributor_part_number: 296-23229-1-ND; Footprint Path: Y:\MIS_DATABASE\Library\ALTIUM_TOOL\PCB_FOOTPRINTS\Altium_Footprint_Lib.PcbLib; Height: 0.60MM; Library Path: Y:\MIS_DATABASE\Library\ALTIUM_TOOL\SCHEMATICS_PARTS\MS_GATE_Library.schlib; Mfr_name: TEXAS INSTRUMENTS; Mistral Part No: 141020100014-R; Package: SOT553-5; Part_type: ICS\DIGITAL\GATES; Project: AM64X_SKEVM; RoHS: RoHS; Temperature: -40°C+125°C; Tolerance: NA; Voltage: NA; Wattage: NA; Weight: 2.8mg; Datasheet: Y:\MIS_DATABASE\DATASHEETS\ICS\DIGITAL\GATES\SN74AHC1G02XX.PDF
U20 = TUSB320LAI_X2QFN12: IC USB TYPE-C CHANNEL LOGIC AND PORT CONTROL X2QFN12; Chkd/date: MANIRAJA/210920; Crtd /date: ALVY/210920; Custom_Duty: 15%; Customs_HS_Code: 85423100; Distributor_name: DIGIKEY; Distributor_part_number: 296-TUSB320LAIRWBRCT-ND; Footprint Path: Y:\MIS_DATABASE\Library\ALTIUM_TOOL\PCB_FOOTPRINTS\Altium_Footprint_Lib.PcbLib; Height: 0.40MM; Library Path: Y:\MIS_DATABASE\Library\ALTIUM_TOOL\SCHEMATICS_PARTS\MS_MISCINTERFACE_Library.schlib; Mfr_name: TEXAS INSTRUMENTS; Mistral Part No: 141020090030-R; Package: X2QFN12; Part_type: ICS\INTERFACE; Project: AM64X_SKEVM; RoHS: RoHS; Temperature: -40°C+85°C; Tolerance: NA; Voltage: NA; Wattage: NA; Weight: 5mg; Datasheet: Y:\MIS_DATABASE\DATASHEETS\ICS\INTERFACE\TUSB320LAI.PDF
U23 = TPS22965DSGT_WSON8: IC 5.7V 6A 1-CHANNEL 16mE ON-RESISTANCE LOAD SWITCH WSON8; Chkd/date: MANIRAJA/080817; Crtd /date: VASANTHA/280714; Custom_Duty: 15%; Customs_HS_Code: 85423100; Distributor_name: DIGIKEY; Distributor_part_number: 296-34943-1-ND; Footprint Path: Y:\MIS_DATABASE\Library\ALTIUM_TOOL\PCB_FOOTPRINTS\Altium_Footprint_Lib.PcbLib; Height: 0.80MM; Library Path: Y:\MIS_DATABASE\Library\ALTIUM_TOOL\SCHEMATICS_PARTS\MS_MISCPOWER_Library.schlib; Mfr_name: TEXAS INSTRUMENTS; Mistral Part No: 142014070020-R; Package: WSON8; Part_type: ICS\POWER\DRIVER; Project: DC_MIST_DIGITAL CARD; RoHS: RoHS; Temperature: -40°C+105°C; Tolerance: NA; Voltage: NA; Wattage: NA; Weight: 11mg; Datasheet: Y:\MIS_DATABASE\DATASHEETS\ICS\POWER\TPS22965-SER.PDF

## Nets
DGND: C42.2 C57.2 C63.2 C64.2 C65.2 C66.2 C67.2 C68.2 C69.2 C70.2 C109.2 C116.2 C126.2 C135.2 C142.2 C144.2 C147.2 C148.2 C153.2 C156.2 C157.2 C162.2 C174.2 C176.2 C177.2 C178.2 C179.2 C184.2 C185.2 C189.2 C190.2 C193.2 C194.2 C198.2 C204.2 C206.2 C210.2 C224.2 C225.2 C232.2 C236.2 C241.2 C266.2 D3.1(A) D6.2(ANODE) D7.2(ANODE) D8.2(ANODE) J10.A1(GND) J10.A12(GND) J10.B1(GND) J10.B12(GND) J10.G1(GND) J10.G2(GND) LD7.1(CATHODE) R83.1 R92.1 R116.1 R119.1 R160.2 R239.2 R255.2 U15.3(GND) U20.10(GND) U20.11(EN_N) U23.5(GND) U23.9(EP) ; also on sheet 10 11 12 13 14 15 16 17 18 19 20 21 22 23 24 27 28
VBUS_DETECT: R113.1 U20.4(VBUS_DET)
VBUS_TYPEC: C68.1 C70.1 D8.1(CATHODE) FL1.1 J10.A4(VBUS1) J10.A9(VBUS2) J10.B4(VBUS3) J10.B9(VBUS4) TP32.1(TP)
VDD_1V8: C162.1 FB1.1 FB2.1 FB5.1 FB6.1 FB7.1 FB8.1 FB9.1 U18.F14(VMON_1P8_SOC) ; also on sheet 10 12 28
VDD_CORE_0V85: U18.V16(VDDA_0P85_USB0) ; also on sheet 10 24 27
VDDA_1P8_USB0: C176.1 C177.1 C179.1 FB5.2 TP47.1(TP) U18.U15(VDDA_1P8_USB0)
VDDA_1V8: C126.1 C135.1 C144.1 C153.1 FB2.2 TP40.1(TP) U18.F18(VDDS_OSC) U18.H14(VDDA_MCU) ; also on sheet 10
VDDA_3P3_USB0: C156.1 C157.1 C178.1 FB4.2 TP45.1(TP) U18.U16(VDDA_3P3_USB0)
VDDA_3V3: C142.1 C174.1 FB3.2 TP43.1(TP) U18.K15(VDDA_3P3_SDIO)
VDDA_ADC: C109.1 C116.1 C147.1 C148.1 FB1.2 TP48.1(TP) U18.G17(VDDA_ADC) U18.H17(VDDA_ADC)
VDDA_PLL0: C185.1 C204.1 C206.1 FB7.2 TP41.1(TP) U18.N12(VDDA_PLL0)
VDDA_PLL1: C210.1 C236.1 C241.1 FB9.2 TP44.1(TP) U18.G9(VDDA_PLL1)
VDDA_PLL2: C184.1 C193.1 C194.1 FB6.2 TP46.1(TP) U18.G12(VDDA_PLL2)
VDDA_TEMP: C190.1 C198.1 C224.1 C225.1 FB8.2 TP42.1(TP) U18.G11(VDDA_TEMP0) U18.M11(VDDA_TEMP1)
VDDSHV_3V3: C189.1 U18.E15(VMON_3P3_SOC) ; also on sheet 24
TUSB_ADDR: TP29.1(TP) U20.5(ADDR)
TUSB_ID: TP28.1(TP) U20.9(ID)
TUSB_INT_N: R110.1 U20.6(INT_N/OUT3)
TUSB_OUT1: R107.1 U15.2(B)
TUSB_OUT1_R: R106.1 R107.2 U20.7(SDA/OUT1)
TUSB_OUT2: R92.2 R104.1 U15.1(A)
TUSB_OUT2_R: R104.2 R105.1 U20.8(SCL/OUT2)
TYPEC_CC1: J10.A5(CC1) U20.1(CC1)
TYPEC_CC2: J10.B5(CC2) U20.2(CC2)
TYPEC_DN: D6.1(CATHODE) J10.A7(DN1) J10.B7(DN2) L3.2(IN2)
TYPEC_DP: D7.1(CATHODE) J10.A6(DP1) J10.B6(DP2) L3.3(OUT1)
USB0_DN: L3.1(IN1) U18.AA17(USB0_DM)
USB0_DP: L3.4(OUT2) U18.AA16(USB0_DP)
USB0_DRVVBUS: TP21.1(TP) U18.B19(USB0_DRVVBUS)
USB0_ID: R83.2 U18.Y17(USB0_ID)
USB0_RCALIB: R239.1 U18.W17(USB0_RCALIB)
USB0_VBUS: R116.2 R118.2 U18.V18(USB0_VBUS)
USBC_SHIELD: C266.1 J10.SH1 J10.SH2 J10.SH3 J10.SH4 J10.SH5 J10.SH6 R160.1
VMON_VSYS: C232.1 R255.1 R262.2 U18.G13(VMON_VSYS)
VSYS_3V3: FB3.1 FB4.1 ; also on sheet 10 11 12 13 14 15 16 17 18 19 20 21 22 23 24 27 28
VSYS_5V0: C63.1 C64.1 R86.1 R117.1 R262.1 TP39.1(TP) U23.7(VOUT1) U23.8(VOUT2) ; also on sheet 10 13 14 19 20 27 28
VSYS_5V0_CT: C69.1 U23.6(CT)
VSYS_5V0_ON: LD9.1(CATHODE) U15.4(Y) U23.3(ON)
VUSB_5V0: C42.1 C57.1 C65.1 C66.1 C67.1 FL1.2 R94.1 R105.2 R106.2 R110.2 R113.2 TP53.1(TP) U15.5(VCC) U20.12(VDD) U23.1(VIN1) U23.2(VIN2) U23.4(VBIAS) ; also on sheet 20
N30310219: D3.3(C) R117.2 R118.1
N30703604: LD7.2(ANODE) R86.2
N31458583: R119.2 U20.3(PORT)
N31483389: LD9.2(ANODE) R94.2

Not connected (* = marked no-connect by the designer): D3 2(NC)*; J10 A2(SSTXP1)* A3(SSTXN1)* A8(SBU1)* A10(SSRXN2)* A11(SSRXP2)* B2(SSTXP2)* B3(SSTXN2)* B8(SBU2)* B10(SSRXN1)* B11(SSRXP1)*

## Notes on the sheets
sheet 25
- SoC Analog POWER & DECAPs
- VDDA_1V8 DECAPs
- VDDA_3V3 DECAPs
- VDD_1V8 & VDDSHV_3V3 DECAP
  (Should be placed near to corresponding
  SoC Balls)
- VDDA_PLL0 DECAPs
- VDDA_PLL1 DECAPs
- VDDA_PLL2 DECAPs
- VDDA_TEMP DECAPs
- VDDA_3P3_USB0 DECAPs
- VDDA_1P8_USB0 DECAPs
- VDDA_ADC DECAPs
sheet 26
- Type C Connector for Power Input & USB2.0
- Resistor divider on SOC_VBUS
- CC Logic controller
- RED
- Power Error
  indication LED
- GREEN
- Power Indicator LED
- Load Switch for Board input Power
